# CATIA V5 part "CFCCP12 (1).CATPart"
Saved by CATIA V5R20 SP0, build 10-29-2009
Part number: CFCCP12 (1)
Revision: TUTTO
Definition: NON CONOSCIUTO
Nomenclature: CFCCP12 (1)
Source: Unknown
Bounding box of the stored display mesh (mm): x -60 to 60, y -60 to 60, z 0 to 10.5
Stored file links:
  C:\Users\Utente\Desktop\IO LAVORO\3D X SITO CF\X 3D SITO CF 27-09-2020\CFCCP\CFCCP12\CFCCP12 (1).CATPart
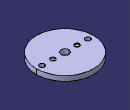
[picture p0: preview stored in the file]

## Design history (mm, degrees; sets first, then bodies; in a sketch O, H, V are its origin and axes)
Body1 "Foro Ø5.5 (5.5)-1" (main body)
  Solid1: solid without history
